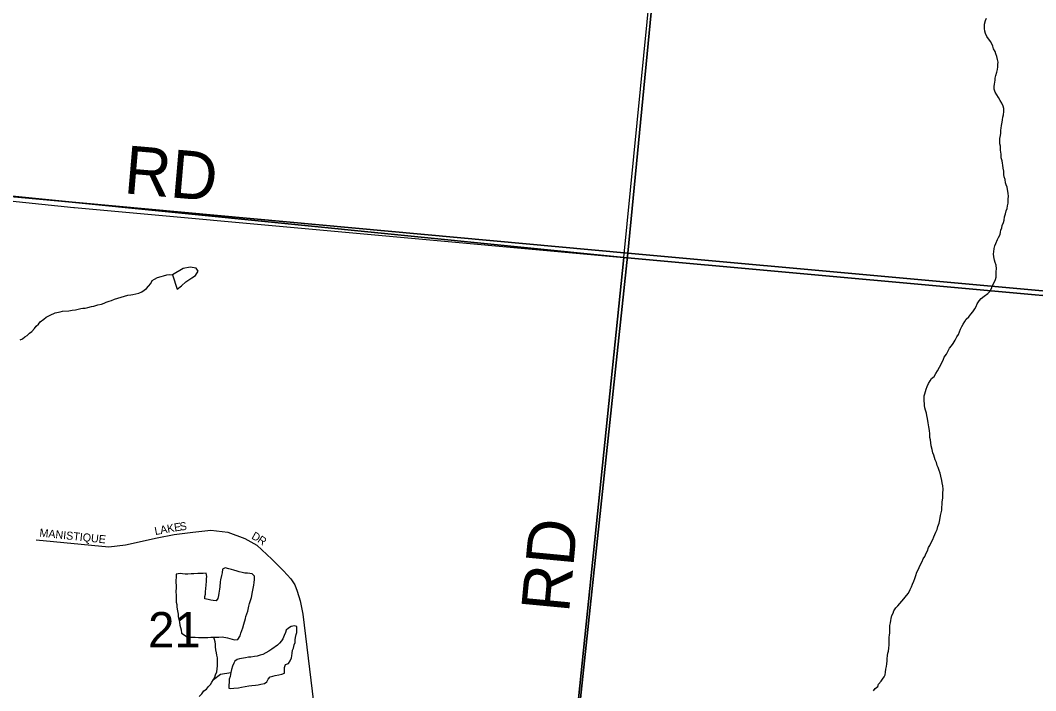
# Model space of a CAD drawing. Extents: x 1310247 to 1664935, y 284496 to 704931.
# Drawn here: x 1497662 to 1504004, y 511730 to 515913 of the extents above; entities that cross this region are included whole.
import ezdxf

# ---------------------------------------------------------------- set-up
doc = ezdxf.new("R2010")
doc.units = 0
for name, color, linetype in [('GM_P_State_Location', 7, 'Continuous'), ('GM_X_Adjacent_County', 7, 'Continuous'), ('GM_X_County', 7, 'Continuous'), ('GM_X_County_Subdivision_Text', 7, 'Continuous'), ('GM_X_Minor_River', 7, 'Continuous'), ('GM_X_Minor_River_Text', 7, 'Continuous'), ('GM_X_State_Location', 7, 'Continuous'), ('GM_X_Township_Subdivision', 7, 'Continuous'), ('GM_X_US_Location', 7, 'Continuous')]:
    doc.layers.add(name, color=color, linetype=linetype)

msp = doc.modelspace()

# ---------------------------------------------------------------- linework, layer by layer
at = {"layer": 'GM_X_Adjacent_County'}
for points in [[(1512140, 513465.9), (1508014.5, 513835.1), (1507776.5, 513856.4), (1506824.4, 513944.8), (1506638.7, 513961.6), (1506616.4, 513963.6), (1501430.9, 514433.2), (1494413.1, 515137), (1494389.6, 515139.4), (1494077.2, 515169.8)], [(1494077.2, 515169.8), (1494389.6, 515139.4), (1494413.1, 515137), (1501430.9, 514433.2), (1501118.3, 511375.5)], [(1501118.3, 511375.5), (1501430.9, 514433.2), (1506616.4, 513963.6), (1506638.7, 513961.6), (1506824.4, 513944.8), (1507776.5, 513856.4), (1508014.5, 513835.1), (1512140, 513465.9)]]:
    msp.add_lwpolyline(points, dxfattribs=at)
at = {"layer": 'GM_X_County'}
for points in [[(1496845.7, 520606.4), (1502005.1, 520103.9), (1501457.6, 514459.3), (1496329.6, 514931.2)], [(1502005.1, 520103.9), (1507180.6, 519609.2), (1506637.6, 513990.6), (1501457.6, 514459.3)], [(1501457.6, 514459.3), (1500914.6, 509372.6), (1495825.8, 509911.6), (1496329.6, 514931.2)], [(1501457.6, 514459.3), (1506637.6, 513990.6), (1506128.6, 508801.3), (1500914.6, 509372.6)]]:
    msp.add_lwpolyline(points, close=True, dxfattribs=at)
at = {"layer": 'GM_X_County_Subdivision_Text'}
for points in [[(1501430.9, 514433.2), (1501430.9, 514433.2), (1501722.1, 517377.3), (1501771.5, 517702.4)], [(1494536.2, 514960.6), (1494618.2, 514997.1), (1494763.4, 515039.9), (1494862.3, 515058.6), (1494956.7, 515061.3), (1497997.7, 514745.3), (1498000.7, 514745.1)], [(1498000.7, 514745.1), (1501430.9, 514433.2)], [(1501072, 511344.4), (1501084.8, 511353), (1501118.3, 511375.5), (1501430.9, 514433.2)]]:
    msp.add_lwpolyline(points, dxfattribs=at)
at = {"layer": 'GM_X_Minor_River'}
for points in [[(1498613.8, 514324.8), (1498641.8, 514235.8), (1498668.4, 514257.2), (1498697.1, 514280.6), (1498733.9, 514305.8), (1498756.4, 514321.3), (1498773.2, 514349), (1498761.5, 514367.3), (1498723.5, 514372.3), (1498679.1, 514365.3)], [(1498679.1, 514365.3), (1498613.8, 514324.8)], [(1498870.5, 512063.4), (1498902, 512064.4), (1498922.1, 512065.8), (1498956.1, 512060.8), (1498972, 512056.2), (1498999.9, 512047.4), (1499020, 512048.8), (1499034.9, 512072.3), (1499039.4, 512088.2), (1499046, 512106.1), (1499052.6, 512121.9), (1499059.4, 512145.7), (1499068.5, 512179.5), (1499071, 512193.4), (1499084.2, 512227.1), (1499089.2, 512257), (1499093.8, 512274.9), (1499107.1, 512312.5), (1499112.2, 512346.4), (1499117, 512368.3), (1499121.7, 512388.2), (1499122.2, 512404.2), (1499124.9, 512424.2), (1499125.5, 512444.2), (1499109.9, 512458.7), (1499095.9, 512461.1), (1499082, 512463.6), (1499063.9, 512464.1), (1499047.9, 512466.6), (1499030, 512471.2), (1499016, 512475.6), (1498996.2, 512482.3), (1498982.2, 512486.7), (1498964.3, 512491.3), (1498942.4, 512495.9), (1498926, 512488.4), (1498923.3, 512466.5), (1498918.7, 512448.6), (1498911.8, 512422.8), (1498911.4, 512408.8), (1498908.4, 512378.8), (1498905.8, 512362.8), (1498903, 512338.9), (1498900.6, 512324.9), (1498895.9, 512305), (1498885.4, 512291.3), (1498867.3, 512291.9), (1498853.3, 512294.3), (1498835.4, 512298.9), (1498815.5, 512303.5), (1498815.9, 512317.5), (1498818.4, 512331.5), (1498818.9, 512347.5), (1498821.6, 512367.4), (1498822.3, 512389.5), (1498825.1, 512413.4), (1498825.6, 512427.4), (1498828.1, 512443.4), (1498822.8, 512463.6), (1498804.6, 512462.1), (1498788.5, 512460.6), (1498770.4, 512461.2), (1498746.3, 512459.9), (1498730.1, 512458.4), (1498708, 512457.1), (1498691.9, 512457.6), (1498676, 512460.1), (1498659.9, 512460.6), (1498635.7, 512457.3), (1498635, 512437.3), (1498634.4, 512419.3), (1498633.9, 512403.3), (1498635.4, 512389.2), (1498635, 512375.2), (1498634, 512345.2), (1498635.5, 512329.1), (1498636.5, 512299), (1498635.9, 512283), (1498639.4, 512266.9), (1498641, 512252.8), (1498642.5, 512238.7), (1498647.5, 512206.5), (1498649, 512190.4), (1498655.9, 512158.2), (1498659.3, 512138), (1498666.4, 512109.8), (1498669.7, 512089.6)], [(1498669.7, 512089.6), (1498705.1, 512066.5), (1498719.1, 512064.1), (1498735.2, 512063.6), (1498755.3, 512063), (1498775.3, 512062.3), (1498803.4, 512061.5), (1498833.6, 512062.5), (1498851.7, 512064), (1498870.5, 512063.4)], [(1498963.8, 511746), (1498977.8, 511743.5), (1498995.9, 511745), (1499024.2, 511748.1), (1499044.4, 511751.5), (1499088.9, 511760.1), (1499109, 511761.5), (1499131.2, 511764.8), (1499147.3, 511766.3), (1499165.5, 511769.8), (1499187.8, 511775.1), (1499202.2, 511784.7), (1499210.8, 511802.4), (1499223.3, 511816.1), (1499239.6, 511821.6), (1499253.7, 511825.2), (1499278, 511828.4), (1499296.2, 511833.9), (1499312.5, 511839.4), (1499313.1, 511857.4), (1499311.7, 511875.5), (1499318.3, 511893.3), (1499336.6, 511900.7), (1499347.2, 511916.4), (1499355.8, 511934.2), (1499358.3, 511948.2), (1499360.8, 511964.1), (1499363.4, 511982.1), (1499367.9, 511996), (1499372.6, 512015.8), (1499379.1, 512031.7), (1499379.7, 512047.7), (1499382.1, 512061.6), (1499384.7, 512079.6), (1499389.2, 512093.5), (1499389.8, 512111.5), (1499388.5, 512131.5), (1499374.5, 512134), (1499354.3, 512130.6), (1499337.9, 512121.1), (1499323.4, 512107.5), (1499318.9, 512093.6), (1499310.2, 512073.9), (1499301.5, 512054.1), (1499293, 512040.3), (1499280.5, 512026.7), (1499268, 512013.1), (1499233, 511988.1), (1499214.6, 511976.6), (1499196.1, 511965.2), (1499177.7, 511955.7), (1499159.5, 511952.3), (1499141.2, 511944.8), (1499125, 511943.3), (1499102.8, 511940), (1499086.7, 511938.5), (1499068.5, 511935.1), (1499032.1, 511928.2), (1499015.9, 511924.7), (1499001.5, 511915.1), (1498995.1, 511901.3), (1498988.4, 511883.4), (1498981.7, 511861.6), (1498977.5, 511843.6)], [(1498977.5, 511843.6), (1498972.2, 511817.8), (1498967.7, 511801.9), (1498963.8, 511746)]]:
    msp.add_lwpolyline(points, dxfattribs=at)
at = {"layer": 'GM_X_Minor_River_Text'}
for points in [[(1503744.2, 514489.4), (1503748.7, 514505.3), (1503755.3, 514521.1), (1503766.1, 514544.8), (1503772.6, 514558.7), (1503781.2, 514576.4), (1503783.7, 514590.4), (1503786.2, 514604.3), (1503792.6, 514618.2), (1503795.1, 514632.1), (1503801.8, 514652), (1503806.3, 514665.8), (1503809, 514687.8), (1503815.6, 514705.6), (1503820.3, 514725.5), (1503824.8, 514739.4), (1503827.3, 514755.3), (1503831.9, 514773.2), (1503832.8, 514799.2), (1503833.3, 514813.3), (1503832, 514835.3), (1503828.7, 514857.5), (1503825.1, 514871.6), (1503819.6, 514885.8), (1503816, 514899.9), (1503812.7, 514920.1), (1503807.2, 514936.3), (1503805.6, 514950.3), (1503804.4, 514972.4), (1503800.9, 514990.6), (1503799.5, 515008.6), (1503796, 515022.8), (1503794.4, 515036.8), (1503789, 515055), (1503787.8, 515079.1), (1503784.6, 515103.3), (1503783.3, 515127.3), (1503779.9, 515143.5), (1503780.3, 515157.5), (1503780.9, 515175.5), (1503783.6, 515195.5), (1503786.1, 515209.4), (1503786.7, 515227.4), (1503789.1, 515241.4), (1503789.7, 515257.4), (1503794.3, 515277.3), (1503796.9, 515293.2), (1503799.4, 515309.2), (1503801.9, 515323.1), (1503804.6, 515345.1), (1503805.2, 515363.1), (1503801.6, 515377.2), (1503792.2, 515395.5), (1503782.8, 515413.9), (1503771.3, 515432.3), (1503761.8, 515448.6), (1503750.3, 515465), (1503744.9, 515483.2), (1503745.5, 515501.2), (1503745.9, 515515.2), (1503750.7, 515539.1), (1503751.2, 515553.1), (1503755.7, 515569), (1503760.4, 515588.9), (1503765, 515606.8), (1503767.6, 515622.7), (1503768.1, 515638.7), (1503768.6, 515652.7), (1503765.1, 515668.9), (1503761.6, 515687), (1503754.2, 515703.3), (1503750.7, 515719.4), (1503741.2, 515735.7), (1503735.7, 515751.9), (1503724.5, 515778.3), (1503709.1, 515798.8), (1503699.5, 515813.1), (1503690.1, 515831.5), (1503686.5, 515845.6), (1503685, 515861.7), (1503683.5, 515875.8), (1503684, 515889.8), (1503690.7, 515911.6), (1503697.3, 515927.4)], [(1503373.8, 512705.7), (1503380.3, 512719.5), (1503388.9, 512735.3), (1503393.5, 512755.2), (1503400.2, 512775), (1503404.9, 512796.9), (1503409.8, 512822.8), (1503414.4, 512840.7), (1503417, 512856.6), (1503417.6, 512876.6), (1503420.1, 512890.6), (1503420.7, 512908.6), (1503423.4, 512930.6), (1503423.9, 512944.6), (1503424.4, 512960.6), (1503425.4, 512988.6), (1503424, 513008.7), (1503420.6, 513026.8), (1503417, 513041), (1503411.9, 513069.2), (1503406.5, 513087.4), (1503401, 513103.6), (1503395.6, 513121.8), (1503388, 513136), (1503384.6, 513154.1), (1503375.1, 513170.5), (1503371.5, 513184.6), (1503368, 513198.8), (1503362.5, 513215), (1503357.1, 513235.1), (1503351.9, 513257.3), (1503347.1, 513295.6), (1503343.5, 513309.7), (1503342.3, 513333.8), (1503341, 513353.8), (1503335.7, 513376.1), (1503332.5, 513402.2), (1503327.4, 513428.4), (1503323.9, 513446.5), (1503322.5, 513462.6), (1503315, 513480.9), (1503311.5, 513495), (1503309.9, 513509.1), (1503308.4, 513523.2), (1503306.8, 513537.2), (1503307.3, 513551.2), (1503307.9, 513569.3), (1503312.4, 513583.1), (1503314.9, 513597.1), (1503319.3, 513611), (1503325.9, 513628.8), (1503334.6, 513646.6), (1503345.2, 513664.3), (1503353.7, 513678), (1503370.2, 513691.5), (1503380.8, 513709.2), (1503391.5, 513727), (1503402.2, 513748.7), (1503412.9, 513768.4), (1503428, 513798), (1503432.5, 513811.8), (1503447.1, 513829.4), (1503453.6, 513843.2), (1503466.4, 513866.9), (1503479, 513882.5), (1503487.5, 513896.3), (1503500.3, 513917.9), (1503511, 513937.6), (1503521.5, 513953.3), (1503528.1, 513969.2), (1503534.7, 513987), (1503543.3, 514002.8), (1503551.7, 514016.5), (1503560.4, 514034.3), (1503568.9, 514048), (1503585.4, 514063.6), (1503598, 514079.2), (1503610.6, 514094.8), (1503623.2, 514112.5), (1503631.8, 514128.3), (1503638.3, 514144.1), (1503651, 514163.7), (1503663.5, 514177.4), (1503682.1, 514192.8), (1503704.8, 514208.1), (1503717.3, 514221.8), (1503727.9, 514239.5), (1503732.4, 514255.4), (1503743.1, 514273.1), (1503751.9, 514296.8), (1503756.4, 514310.7), (1503757, 514330.8), (1503757.6, 514346.8), (1503758.1, 514362.8), (1503756.8, 514384.8), (1503751.4, 514403), (1503745.8, 514417.2), (1503742.5, 514437.4), (1503741.1, 514455.5), (1503741.5, 514469.5), (1503744.2, 514489.4)], [(1497661.2, 513919.9), (1497675.5, 513925.5), (1497690, 513939.1), (1497704.3, 513946.7), (1497720.8, 513960.2), (1497735.3, 513971.8), (1497752, 513989.3), (1497762.5, 514005), (1497777, 514016.5), (1497787.5, 514032.3), (1497810.1, 514047.6), (1497824.7, 514061.2), (1497849.2, 514074.4), (1497879.8, 514087.5), (1497912.2, 514094.5), (1497926.3, 514098.1), (1497964.6, 514100.9), (1497986.8, 514104.2), (1498007, 514107.6), (1498023.2, 514111.1), (1498039.4, 514114.6), (1498053.5, 514116.2), (1498067.6, 514117.8), (1498083.8, 514121.3), (1498106.1, 514126.6), (1498122.3, 514130.1), (1498146.6, 514137.4), (1498168.9, 514142.7), (1498185.2, 514148.2), (1498199.4, 514153.8), (1498217.8, 514161.2), (1498231.9, 514164.8), (1498250.3, 514174.2), (1498270.6, 514179.6), (1498292.9, 514185), (1498313.2, 514192.3), (1498333.5, 514197.7), (1498351.7, 514201.2), (1498365.8, 514202.7), (1498384, 514206.2), (1498402.3, 514211.6), (1498420.6, 514219.1), (1498437, 514228.6), (1498451.4, 514240.2), (1498463.9, 514253.8), (1498476.6, 514271.4), (1498485.2, 514289.2), (1498499.6, 514298.8), (1498520, 514308.2), (1498542.4, 514315.5), (1498556.5, 514319.1), (1498576.8, 514324.4), (1498595, 514327.9), (1498613.8, 514324.8)], [(1502989.9, 511729.8), (1503000.4, 511743.5), (1503017, 511757), (1503021.4, 511770.9), (1503038.1, 511788.4), (1503046.6, 511802.2), (1503057.1, 511815.9), (1503063.6, 511829.7), (1503066.1, 511845.7), (1503068.7, 511863.6), (1503071.3, 511881.6), (1503073.8, 511897.5), (1503076.4, 511915.5), (1503076.9, 511929.5), (1503077.6, 511949.5), (1503080, 511963.4), (1503084.5, 511977.3), (1503087.1, 511995.3), (1503087.8, 512015.3), (1503088.3, 512031.3), (1503088.8, 512045.3), (1503089.4, 512063.3), (1503091.8, 512077.3), (1503092.3, 512091.3), (1503092.8, 512105.3), (1503093.2, 512119.3), (1503093.8, 512137.3), (1503096.4, 512153.3), (1503098.8, 512167.2), (1503101.3, 512181.2), (1503105.9, 512199.1), (1503114.5, 512214.8), (1503118.9, 512228.7), (1503129.6, 512246.4), (1503142.1, 512260), (1503154.6, 512273.7), (1503167.2, 512289.3), (1503179.7, 512303), (1503196.4, 512324.5), (1503209, 512338.1), (1503219.8, 512361.8), (1503228.3, 512377.6), (1503235, 512395.4), (1503243.6, 512413.2), (1503248.2, 512431.1), (1503254.8, 512448.9), (1503261.5, 512468.8), (1503270.1, 512484.5), (1503276.5, 512498.3), (1503285.2, 512518.1), (1503293.9, 512535.9), (1503300.5, 512553.7), (1503311, 512567.4), (1503319.7, 512589.2), (1503328.2, 512602.9), (1503334.9, 512622.7), (1503343.4, 512636.5), (1503352.2, 512658.3), (1503360.7, 512674), (1503367.3, 512689.9), (1503373.8, 512705.7)], [(1498779.2, 511693.5), (1498795.9, 511711.1), (1498808.5, 511728.7), (1498825, 511740.2), (1498837.5, 511755.9), (1498850, 511769.5), (1498858.5, 511783.3), (1498869.1, 511799), (1498877.7, 511814.7), (1498882.1, 511828.6), (1498888.8, 511848.5), (1498891.4, 511866.4), (1498894, 511884.3), (1498894.5, 511898.4), (1498893.1, 511916.4), (1498893.7, 511934.5), (1498890.3, 511952.6), (1498888.7, 511966.7), (1498883.3, 511984.9), (1498881.9, 512002.9), (1498880.5, 512021), (1498878.9, 512035.1), (1498870.5, 512063.4)], [(1498869.1, 511799), (1498912.4, 511833.7), (1498977.5, 511843.6)]]:
    msp.add_lwpolyline(points, dxfattribs=at)
at = {"layer": 'GM_X_State_Location'}
msp.add_lwpolyline([(1497760.7, 512671.3), (1498215.1, 512628.4), (1498320.3, 512639.6), (1498516.7, 512684.3), (1498622.9, 512704.8), (1498739.3, 512719.7), (1498852.8, 512732.7), (1498958.1, 512719.7), (1499064.2, 512678.7), (1499140.5, 512638.7), (1499233.6, 512551.1), (1499305.3, 512478.5), (1499352.8, 512427.3), (1499377, 512390.1), (1499391.9, 512351), (1499410.6, 512290.4), (1499427.3, 512208.5), (1499492.5, 511659.2), (1499514.8, 511592.2), (1499561.4, 511515.8), (1499652.6, 511495.3), (1499756.9, 511480.4)], dxfattribs=at)

# ---------------------------------------------------------------- texts
at = {"layer": 'GM_P_State_Location'}
for s, rotation, p in [('K', 10.0409, (1498583.4, 512715.6)), ('E', 8.47402, (1498626.4, 512723.2)), ('S', 7.92145, (1498661, 512728.4)), ('MANISTIQUE', 354.02407, (1497780.3, 512692.1)), ('L', 10.82775, (1498505.8, 512700.7)), ('A', 10.8338, (1498540.3, 512707.3)), ('D', 330.71608, (1499102, 512681.3)), ('R', 325.27259, (1499139.3, 512660.4))]:
    msp.add_text(s, height=50, rotation=rotation, dxfattribs=at).set_placement(p)
at = {"layer": 'GM_X_Township_Subdivision'}
for rotation, p in [(355.07189, (1498303.5, 514834.5)), (84.58411, (1501088.7, 512211.3))]:
    msp.add_text('RD', height=300, rotation=rotation, dxfattribs=at).set_placement(p)
at = {"layer": 'GM_X_US_Location'}
msp.add_text('21', height=221, rotation=0.00001, dxfattribs=at).set_placement((1498460.6, 511999.7))

doc.saveas('drawing.dxf')
